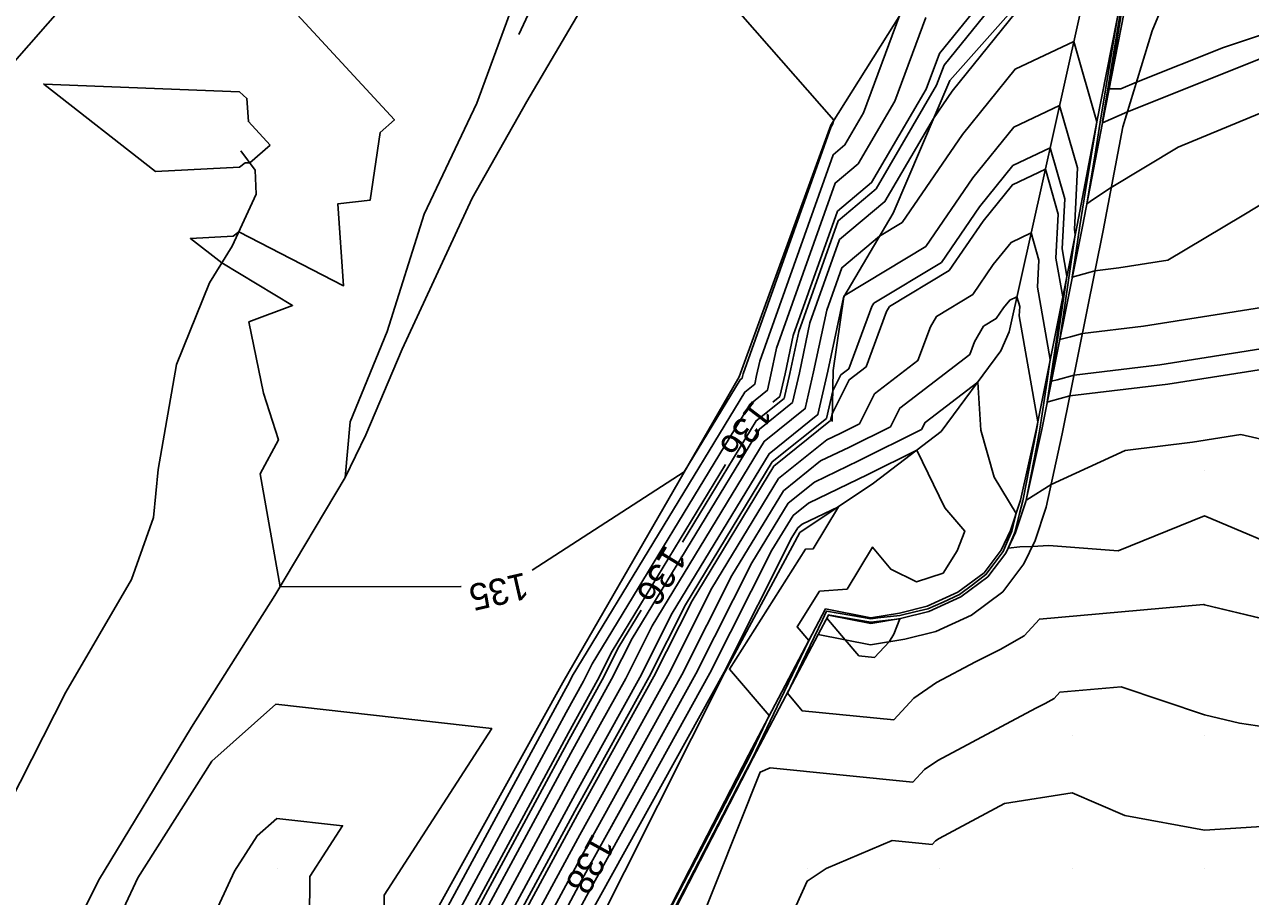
# Model space of a CAD drawing. Extents: x 2354170 to 2357230, y 866100 to 868290.
# Drawn here: x 2354670.9 to 2354763.4, y 867567.9 to 867633.7 of the extents above; entities that cross this region are included whole.
import ezdxf

# ---------------------------------------------------------------- set-up
doc = ezdxf.new("R2010")
doc.units = 0
for name, color, linetype in [('Default', 7, 'Continuous'), ('DTM Contours Major', 7, 'Continuous'), ('DTM Contours Major Text', 7, 'Continuous'), ('DTM Contours Minor', 7, 'Continuous'), ('DTM Contours Minor Text', 7, 'Continuous'), ('Exist DTM QL2 LIDAR Elevation Point', 7, 'Continuous'), ('PH Exist DTM Breakline', 7, 'Continuous')]:
    doc.layers.add(name, color=color, linetype=linetype)

msp = doc.modelspace()

# ---------------------------------------------------------------- linework, layer by layer
at = {"layer": 'Default'}
for points in [[(2354753.289, 867645.149), (2354753.89, 867644.723), (2354753.715, 867644.159), (2354753.483, 867644.183), (2354752.387, 867644.712), (2354749.577, 867645.426), (2354745.199, 867646.843), (2354737.675, 867651.174), (2354735.499, 867649.204), (2354724.939, 867645.727), (2354721.135, 867638.857), (2354732, 867626.487), (2354731.877, 867626.156), (2354731.813, 867626.047), (2354731.774, 867626.014), (2354725.132, 867607.354), (2354725.087, 867607.143), (2354725.059, 867607.018), (2354724.918, 867606.906), (2354720.686, 867599.939), (2354709.214, 867592.527)], [(2354703.858, 867591.296), (2354703.825, 867591.305), (2354690.194, 867591.273), (2354688.692, 867599.791), (2354690.055, 867602.378), (2354688.937, 867605.884), (2354687.836, 867611.265), (2354691.132, 867612.495), (2354685.781, 867615.714), (2354683.422, 867617.564), (2354686.642, 867617.728), (2354687.065, 867618.056), (2354694.979, 867613.992), (2354694.546, 867620.18), (2354696.987, 867620.459), (2354697.732, 867625.558), (2354698.816, 867626.509), (2354690.241, 867635.818), (2354690.032, 867638.88), (2354688.601, 867641.962), (2354688.404, 867642.089), (2354688.216, 867642.692), (2354690.195, 867646.304), (2354690.52, 867647.046)], [(2354669.967, 867630.717), (2354677.868, 867639.745)], [(2354772.251, 867634.306), (2354768.905, 867633.644), (2354767.48, 867634.023), (2354761.394, 867631.986), (2354754.84, 867629.368), (2354753.641, 867628.845), (2354752.763, 867628.867), (2354754.241, 867637.936)], [(2354743.213, 867635.533), (2354739.968, 867631.535), (2354738.962, 867628.825), (2354734.839, 867621.775), (2354732.262, 867619.615), (2354728.923, 867610.234), (2354728.312, 867607.351), (2354727.924, 867605.645), (2354727.389, 867605.217)], [(2354745.77, 867634.683), (2354740.932, 867628.688), (2354739.506, 867626.605), (2354735.848, 867620.351), (2354732.424, 867617.482), (2354730.186, 867611.194), (2354729.387, 867607.421), (2354728.879, 867605.187), (2354726.369, 867603.182), (2354716.763, 867587.372), (2354715.214, 867584.296), (2354712.123, 867578.711), (2354705.438, 867566.346), (2354701.758, 867560.163), (2354693.163, 867547.394), (2354691.86, 867545.154), (2354681.834, 867526.589), (2354679.548, 867527.524), (2354677.78, 867522.793), (2354675.617, 867520.767), (2354672.657, 867519.107), (2354671.849, 867517.269), (2354671.575, 867515.082), (2354662.843, 867505.021)], [(2354736.981, 867634.44), (2354734.239, 867627.046), (2354732.822, 867624.623), (2354731.936, 867623.881), (2354726.395, 867608.314), (2354726.162, 867607.212), (2354726.014, 867606.56), (2354725.281, 867605.975), (2354712.244, 867584.517), (2354712.032, 867584.095), (2354711.608, 867583.329), (2354702.71, 867566.871), (2354702.003, 867565.681), (2354697.987, 867559.716), (2354698.049, 867567.998), (2354706.16, 867580.568), (2354689.864, 867582.409), (2354685.044, 867578.12), (2354679.442, 867569.314), (2354677.287, 867564.679), (2354672.889, 867556.61), (2354670.739, 867550.602)], [(2354703.619, 867566.696), (2354711.779, 867581.79), (2354713.092, 867584.162), (2354713.75, 867585.469), (2354725.644, 867605.044), (2354726.969, 867606.102), (2354727.237, 867607.282), (2354727.659, 867609.274), (2354732.099, 867621.748), (2354733.831, 867623.199), (2354736.601, 867627.936), (2354738.94, 867634.244)], [(2354769.969, 867629.419), (2354757.986, 867624.455), (2354752.932, 867621.408), (2354751.586, 867620.519), (2354751.084, 867620.187), (2354751.754, 867624.247), (2354752.097, 867626.329), (2354753.364, 867634.107)], [(2354766.302, 867621.375), (2354762.808, 867619.269), (2354757.189, 867615.918), (2354753.504, 867615.338), (2354751.697, 867615.119), (2354751.34, 867615.023), (2354749.987, 867614.643), (2354750.18, 867615.955), (2354750.555, 867618.516), (2354750.994, 867621.177), (2354751.849, 867626.364), (2354751.85, 867626.372), (2354750.104, 867632.416), (2354745.67, 867630.328), (2354741.705, 867625.414), (2354737.156, 867618.774), (2354735.442, 867617.742), (2354732.587, 867615.349), (2354731.45, 867612.154), (2354730.462, 867607.491), (2354729.835, 867604.729), (2354726.731, 867602.251), (2354718.269, 867588.323), (2354716.275, 867584.363), (2354712.294, 867577.172), (2354706.347, 867566.171)], [(2354689.437, 867624.612), (2354687.802, 867626.387), (2354687.682, 867628.134), (2354687.134, 867628.62), (2354672.342, 867629.213), (2354680.774, 867622.614), (2354687.116, 867622.937), (2354687.545, 867623.27), (2354687.898, 867623.263), (2354689.437, 867624.612)], [(2354764.74, 867612.432), (2354755.354, 867610.954), (2354750.752, 867610.398), (2354749.841, 867610.151), (2354749.043, 867609.927), (2354749.472, 867612.855), (2354750.208, 867617.867), (2354750.143, 867618.239), (2354750.392, 867622.887), (2354749.029, 867627.603), (2354745.571, 867625.974), (2354742.477, 867622.14), (2354738.928, 867616.961), (2354732.841, 867613.293), (2354732.75, 867613.216), (2354732.713, 867613.114), (2354731.537, 867607.56), (2354730.79, 867604.271), (2354727.094, 867601.32), (2354719.776, 867589.275), (2354717.335, 867584.43), (2354712.466, 867575.633), (2354707.256, 867565.996)], [(2354731.745, 867603.813), (2354731.876, 867604.389), (2354733.142, 867606.905), (2354734.417, 867607.88), (2354735.967, 867612.043), (2354736.183, 867612.425), (2354740.701, 867615.147), (2354743.25, 867618.866), (2354745.471, 867621.62), (2354747.955, 867622.79), (2354748.933, 867619.403), (2354748.755, 867616.065), (2354749.264, 867613.153), (2354748.765, 867609.754), (2354748.098, 867605.212), (2354748.343, 867605.28), (2354749.806, 867605.676), (2354757.204, 867606.57), (2354768.262, 867608.311)], [(2354727.819, 867599.457), (2354731.458, 867602.364), (2354732.47, 867602.853), (2354733.913, 867603.567), (2354735.052, 867605.831), (2354738.336, 867608.344), (2354739.29, 867610.903), (2354739.729, 867611.679), (2354742.474, 867613.333), (2354744.022, 867615.593), (2354745.372, 867617.266), (2354746.881, 867617.976), (2354747.475, 867615.919), (2354747.367, 867613.89), (2354748.32, 867608.439), (2354748.058, 867606.653), (2354747.546, 867603.162), (2354747.284, 867601.804), (2354746.514, 867597.806), (2354746.564, 867597.84), (2354748.397, 867599.002), (2354753.983, 867601.573), (2354759.053, 867602.186), (2354762.713, 867602.763), (2354779.226, 867599.002)], [(2354728.181, 867598.526), (2354730.993, 867600.772), (2354733.163, 867601.82), (2354736.254, 867603.351), (2354736.962, 867604.758), (2354742.256, 867608.808), (2354742.612, 867609.763), (2354743.274, 867610.933), (2354744.246, 867611.519), (2354744.795, 867612.319), (2354745.273, 867612.911), (2354745.807, 867613.163), (2354746.017, 867612.434), (2354745.979, 867611.716), (2354747.376, 867603.725), (2354747.35, 867603.552), (2354747.301, 867603.214), (2354746.572, 867599.426), (2354746.253, 867597.771), (2354746.01, 867596.806), (2354745.651, 867595.39), (2354745.572, 867595.199), (2354745.155, 867594.192), (2354746.035, 867594.279), (2354746.963, 867594.313), (2354748.209, 867594.393), (2354753.447, 867593.983), (2354759.968, 867596.635), (2354774.521, 867590.481)], [(2354728.544, 867597.595), (2354730.528, 867599.18), (2354733.855, 867600.787), (2354738.596, 867603.135), (2354738.873, 867603.685), (2354742.852, 867606.729), (2354743.096, 867603.09), (2354744.082, 867599.551), (2354745.753, 867596.811), (2354745.524, 867595.898), (2354745.419, 867595.484), (2354745.028, 867594.536), (2354744.783, 867593.944), (2354744.092, 867593.024), (2354743.467, 867592.192), (2354742.45, 867591.426), (2354741.462, 867590.681), (2354740.231, 867590.122), (2354739.093, 867589.605), (2354738.106, 867589.378), (2354736.975, 867589.118), (2354735.302, 867588.921), (2354734.789, 867588.86), (2354734.081, 867588.979), (2354731.439, 867589.437), (2354731.125, 867588.782), (2354729.566, 867585.524), (2354728.478, 867583.249), (2354729.594, 867581.925), (2354736.506, 867581.238), (2354738.018, 867582.877), (2354739.748, 867584.039), (2354742.69, 867585.604), (2354744.535, 867586.542), (2354746.348, 867587.562), (2354747.504, 867588.835), (2354759.898, 867589.947), (2354759.968, 867589.924), (2354772.257, 867586.981)], [(2354705.24, 867560.904), (2354708.165, 867565.821), (2354712.637, 867574.093), (2354718.396, 867584.496), (2354721.282, 867590.226), (2354727.456, 867600.389), (2354731.745, 867603.813)], [(2354728.906, 867596.664), (2354730.063, 867597.588), (2354734.548, 867599.754), (2354738.257, 867601.591), (2354740.375, 867597.233), (2354741.881, 867595.48), (2354741.289, 867593.987), (2354740.239, 867592.306), (2354738.219, 867591.657), (2354736.282, 867592.595), (2354734.895, 867594.268), (2354732.988, 867591.09), (2354730.909, 867590.935), (2354729.212, 867588.256), (2354730.102, 867587.223), (2354727.972, 867582.77), (2354725.875, 867578.386), (2354725.075, 867576.849), (2354717.812, 867562.877)], [(2354723.809, 867600.497), (2354715.257, 867586.42), (2354714.153, 867584.229), (2354711.951, 867580.251), (2354704.529, 867566.521), (2354701.84, 867562.002), (2354692.433, 867548.027), (2354691.812, 867546.96), (2354687.037, 867538.118), (2354679.801, 867541.078), (2354674.203, 867526.101), (2354673.03, 867525.003), (2354671.181, 867523.966)], [(2354685.572, 867489.55), (2354682.471, 867491.723), (2354675.058, 867496.562), (2354674.059, 867500.46), (2354674.095, 867501.357), (2354679.343, 867513.255), (2354682.271, 867519.818), (2354683.758, 867522.572), (2354692.051, 867537.928), (2354696.086, 867544.862), (2354701.433, 867552.805), (2354709.075, 867565.646), (2354712.809, 867572.554), (2354719.457, 867584.563), (2354722.788, 867591.178), (2354727.819, 867599.457)], [(2354687.15, 867489.608), (2354682.472, 867492.886), (2354676.177, 867496.995), (2354675.329, 867500.305), (2354675.389, 867501.823), (2354679.862, 867511.964), (2354683.704, 867520.578), (2354684.981, 867522.941), (2354692.099, 867536.122), (2354696.817, 867544.229), (2354701.351, 867550.965), (2354709.984, 867565.471), (2354712.981, 867571.014), (2354720.518, 867584.63), (2354724.295, 867592.129), (2354728.181, 867598.526)], [(2354715.063, 867572.926), (2354721.578, 867584.697), (2354725.801, 867593.081), (2354728.544, 867597.595)], [(2354690.304, 867489.724), (2354682.473, 867495.212), (2354678.414, 867497.861), (2354677.867, 867499.996), (2354677.977, 867502.755), (2354680.9, 867509.383), (2354686.571, 867522.096), (2354687.426, 867523.68), (2354692.194, 867532.509), (2354698.278, 867542.963), (2354701.188, 867547.287), (2354711.802, 867565.121), (2354713.324, 867567.936), (2354722.639, 867584.764), (2354727.307, 867594.032), (2354728.906, 867596.664)], [(2354729.269, 867595.733), (2354729.598, 867595.996), (2354732.335, 867597.318), (2354730.431, 867594.146), (2354729.839, 867594.102), (2354724.105, 867585.046), (2354727.112, 867581.553), (2354726.377, 867580.015), (2354725.653, 867578.502), (2354719.117, 867565.929)], [(2354691.881, 867489.782), (2354682.474, 867496.374), (2354679.533, 867498.294), (2354679.137, 867499.841), (2354679.271, 867503.221), (2354681.419, 867508.093), (2354688.005, 867522.856), (2354688.649, 867524.049), (2354692.242, 867530.702), (2354699.009, 867542.33), (2354701.107, 867545.447), (2354712.712, 867564.946), (2354713.496, 867566.396), (2354723.7, 867584.831), (2354728.814, 867594.984), (2354729.269, 867595.733)], [(2354736.977, 867588.867), (2354734.785, 867588.606), (2354731.675, 867589.131), (2354731.577, 867589.148), (2354731.467, 867588.918), (2354732.851, 867587.275), (2354733.879, 867586.056), (2354735.055, 867585.939), (2354736.154, 867587.13), (2354736.525, 867587.703), (2354736.977, 867588.867)], [(2354721.521, 867564.987), (2354726.432, 867577.287), (2354727.189, 867577.608), (2354737.957, 867576.537), (2354738.835, 867577.489), (2354739.84, 867578.164), (2354747.247, 867582.107), (2354747.936, 867582.457), (2354748.615, 867582.839), (2354749.047, 867583.315), (2354753.682, 867583.731), (2354759.968, 867581.613), (2354762.622, 867580.978), (2354764.66, 867580.684)], [(2354726.264, 867560.881), (2354729.968, 867569.066), (2354731.411, 867570.017), (2354736.403, 867572.135), (2354739.407, 867571.836), (2354739.652, 867572.102), (2354739.933, 867572.29), (2354744.868, 867574.917), (2354749.968, 867575.734), (2354753.963, 867574.012), (2354759.968, 867572.913), (2354766.646, 867573.339)], [(2354679.287, 867553.741), (2354686.756, 867569.803), (2354688.465, 867572.49), (2354689.936, 867573.799), (2354694.909, 867573.237), (2354692.434, 867569.401), (2354692.285, 867549.526)]]:
    msp.add_lwpolyline(points, dxfattribs=at)
at = {"layer": 'DTM Contours Major'}
for points in [[(2354753.289, 867645.149), (2354753.89, 867644.723), (2354753.715, 867644.159), (2354753.483, 867644.183), (2354752.387, 867644.712), (2354749.577, 867645.426), (2354745.199, 867646.843), (2354737.675, 867651.174), (2354735.499, 867649.204), (2354724.939, 867645.727), (2354721.135, 867638.857), (2354732, 867626.487), (2354731.877, 867626.156), (2354731.813, 867626.047), (2354731.774, 867626.014), (2354725.132, 867607.354), (2354725.087, 867607.143), (2354725.059, 867607.018), (2354724.918, 867606.906), (2354720.686, 867599.939), (2354709.214, 867592.527)], [(2354703.858, 867591.296), (2354703.825, 867591.305), (2354690.194, 867591.273), (2354688.692, 867599.791), (2354690.055, 867602.378), (2354688.937, 867605.884), (2354687.836, 867611.265), (2354691.132, 867612.495), (2354685.781, 867615.714), (2354683.422, 867617.564), (2354686.642, 867617.728), (2354687.065, 867618.056), (2354694.979, 867613.992), (2354694.546, 867620.18), (2354696.987, 867620.459), (2354697.732, 867625.558), (2354698.816, 867626.509), (2354690.241, 867635.818), (2354690.032, 867638.88), (2354688.601, 867641.962), (2354688.404, 867642.089), (2354688.216, 867642.692), (2354690.195, 867646.304), (2354690.52, 867647.046)]]:
    msp.add_lwpolyline(points, dxfattribs=at)
at = {"layer": 'DTM Contours Minor'}
for points in [[(2354781.134, 867634.172), (2354779.766, 867633.414), (2354778.958, 867633.082), (2354776.788, 867632.134), (2354776.453, 867631.963), (2354776.243, 867631.88), (2354773.332, 867632.336), (2354771.413, 867632.732), (2354769.295, 867632.313), (2354768.393, 867632.553), (2354764.541, 867631.264), (2354754.155, 867627.115), (2354752.274, 867626.295), (2354752.258, 867626.285), (2354752.26, 867626.294), (2354752.26, 867626.298), (2354752.276, 867626.394), (2354754.159, 867637.952)], [(2354744.168, 867635.386), (2354740.31, 867630.633), (2354739.75, 867629.122), (2354735.175, 867621.301), (2354732.316, 867618.904), (2354729.344, 867610.554), (2354728.67, 867607.375), (2354728.243, 867605.492), (2354726.127, 867603.802), (2354720.561, 867594.641)], [(2354731.427, 867603.966), (2354731.904, 867606.069), (2354732.505, 867607.262), (2354733.11, 867607.725), (2354734.86, 867612.423), (2354735.001, 867612.673), (2354740.11, 867615.751), (2354742.992, 867619.958), (2354745.505, 867623.071), (2354748.313, 867624.394), (2354749.419, 867620.565), (2354749.218, 867616.789), (2354749.579, 867614.724), (2354749.001, 867610.787), (2354748.413, 867606.783), (2354748.842, 867606.904), (2354750.121, 867607.25), (2354756.587, 867608.031), (2354769.774, 867610.108)], [(2354728.544, 867597.595), (2354730.528, 867599.18), (2354733.855, 867600.787), (2354738.596, 867603.135), (2354738.873, 867603.685), (2354742.852, 867606.729), (2354743.096, 867603.09), (2354744.082, 867599.551), (2354745.753, 867596.811), (2354745.524, 867595.898), (2354745.419, 867595.484), (2354745.028, 867594.536), (2354744.783, 867593.944), (2354744.092, 867593.024), (2354743.467, 867592.192), (2354742.45, 867591.426), (2354741.462, 867590.681), (2354740.231, 867590.122), (2354739.093, 867589.605), (2354738.106, 867589.378), (2354736.975, 867589.118), (2354735.302, 867588.921), (2354734.789, 867588.86), (2354734.081, 867588.979), (2354731.439, 867589.437), (2354731.125, 867588.782), (2354729.566, 867585.524), (2354728.478, 867583.249), (2354729.594, 867581.925), (2354736.506, 867581.238), (2354738.018, 867582.877), (2354739.748, 867584.039), (2354742.69, 867585.604), (2354744.535, 867586.542), (2354746.348, 867587.562), (2354747.504, 867588.835), (2354759.898, 867589.947), (2354759.968, 867589.924), (2354776.443, 867585.978)], [(2354720.259, 867466.24), (2354706.626, 867476.082), (2354705.641, 867476.677), (2354699.334, 867479.414), (2354697.435, 867480.463), (2354683.469, 867489.473), (2354682.47, 867490.173), (2354673.566, 867495.985), (2354672.367, 867500.667), (2354672.37, 867500.736), (2354678.651, 867514.975), (2354680.36, 867518.806), (2354682.128, 867522.08), (2354691.987, 867540.336), (2354695.112, 867545.706), (2354701.541, 867555.258), (2354707.862, 867565.879), (2354712.58, 867574.606), (2354718.043, 867584.474), (2354720.78, 867589.909), (2354727.335, 867600.699), (2354731.427, 867603.966)], [(2354710.157, 867477.416), (2354708.532, 867478.397), (2354704.849, 867479.996), (2354696.983, 867484.34), (2354688.727, 867489.666), (2354682.473, 867494.049), (2354677.295, 867497.428), (2354676.598, 867500.15), (2354676.683, 867502.289), (2354680.381, 867510.674), (2354685.138, 867521.337), (2354686.204, 867523.311), (2354692.146, 867534.315), (2354697.548, 867543.596), (2354701.27, 867549.126), (2354710.893, 867565.296), (2354713.152, 867569.475), (2354721.578, 867584.697), (2354725.801, 867593.081), (2354728.544, 867597.595)], [(2354717.446, 867589.514), (2354715.759, 867586.737), (2354714.507, 867584.251), (2354712.008, 867579.738), (2354704.832, 867566.462), (2354701.813, 867561.389), (2354692.676, 867547.816), (2354691.828, 867546.358), (2354685.303, 867534.275), (2354679.717, 867536.56), (2354675.395, 867524.998), (2354673.892, 867523.591), (2354668.461, 867520.544)]]:
    msp.add_lwpolyline(points, dxfattribs=at)
at = {"layer": 'Exist DTM QL2 LIDAR Elevation Point'}
for p, q in [((2354759.968, 867600.018), (2354759.968, 867600.018)), ((2354759.968, 867590.017), (2354759.968, 867590.017)), ((2354749.968, 867580.017), (2354749.968, 867580.017)), ((2354759.968, 867580.017), (2354759.968, 867580.017)), ((2354689.968, 867570.017), (2354689.968, 867570.017)), ((2354729.968, 867570.017), (2354729.968, 867570.017)), ((2354739.968, 867570.017), (2354739.968, 867570.017)), ((2354749.968, 867570.017), (2354749.968, 867570.017)), ((2354759.968, 867570.017), (2354759.968, 867570.017))]:
    msp.add_line(p, q, dxfattribs=at)
at = {"layer": 'PH Exist DTM Breakline'}
for p, q in [((2354751.852, 867626.377), (2354754.118, 867637.96)), ((2354752.261, 867626.298), (2354754.527, 867637.88))]:
    msp.add_line(p, q, dxfattribs=at)
for points in [[(2354708.221, 867632.948), (2354712.344, 867641.814), (2354717.715, 867652.332), (2354721.936, 867661.543), (2354722.309, 867663.296)], [(2354754.118, 867637.96), (2354753.744, 867641.141), (2354752.778, 867642.129), (2354744.152, 867646.615), (2354734.656, 867653.3), (2354729.343, 867657.983), (2354725.013, 867660.602), (2354720.232, 867649.079), (2354715.727, 867639.665), (2354708.808, 867627.903), (2354704.684, 867620.603), (2354699.404, 867609.199), (2354696.662, 867602.739), (2354695.094, 867599.514)], [(2354753.816, 867625.999), (2354756.012, 867633.222), (2354758.46, 867639.139)], [(2354829.923, 867427.32), (2354817.709, 867428.865), (2354759.654, 867457.926), (2354748.772, 867463.94), (2354718.087, 867477.789), (2354712.589, 867480.813), (2354696.33, 867489.946), (2354682.476, 867499.433), (2354682.859, 867504.514), (2354692.388, 867525.178), (2354700.896, 867540.695), (2354713.678, 867564.76), (2354723.77, 867584.835), (2354729.413, 867595.363), (2354734.99, 867599.095), (2354740.097, 867602.997), (2354744.591, 867609.084), (2354745.218, 867610.524), (2354751.239, 867637.503)], [(2354738.155, 867636.314), (2354731.766, 867626.114), (2354724.833, 867607.126), (2354711.526, 867584.063), (2354702.061, 867566.996), (2354691.768, 867548.603), (2354677.681, 867517.387), (2354672.226, 867500.684), (2354673.389, 867495.916), (2354682.47, 867489.436), (2354697.578, 867479.229), (2354703.979, 867475.688), (2354722.591, 867463.336), (2354738.582, 867453.622), (2354742.679, 867450.771), (2354747.113, 867448.158), (2354755.857, 867445.272), (2354761.221, 867443.293), (2354770.34, 867439.958), (2354791.969, 867430.541), (2354800.951, 867426.618), (2354813.493, 867420.185), (2354830.452, 867410.182)], [(2354667.129, 867550.83), (2354671.124, 867558.254), (2354676.476, 867569.116), (2354683.493, 867580.672), (2354689.796, 867590.605), (2354695.094, 867599.514), (2354695.479, 867603.726), (2354698.261, 867610.547), (2354701.075, 867619.398), (2354705.047, 867627.769), (2354707.735, 867635.093)], [(2354745.78, 867635.137), (2354740.741, 867629.496), (2354736.461, 867619.485), (2354732.755, 867613.146), (2354731.93, 867607.586), (2354731.865, 867603.756)], [(2354751.852, 867626.377), (2354750.346, 867618.557), (2354747.275, 867603.219), (2354746.089, 867597.816), (2354745.323, 867595.522), (2354744.622, 867594.041), (2354743.326, 867592.335), (2354741.351, 867590.869), (2354739.023, 867589.805), (2354736.941, 867589.283), (2354734.79, 867588.935), (2354731.358, 867589.605)], [(2354752.261, 867626.298), (2354750.755, 867618.477), (2354747.682, 867603.134), (2354746.492, 867597.705), (2354745.71, 867595.367), (2354744.98, 867593.824), (2354743.622, 867592.036), (2354741.564, 867590.508), (2354739.162, 867589.41), (2354737.025, 867588.875), (2354734.784, 867588.511), (2354731.582, 867589.137)], [(2354753.816, 867625.999), (2354752.309, 867618.172), (2354749.232, 867602.808), (2354748.02, 867597.283), (2354747.182, 867594.775), (2354746.341, 867592.997), (2354744.747, 867590.899), (2354742.374, 867589.137), (2354739.688, 867587.909), (2354737.344, 867587.323), (2354734.758, 867586.903), (2354730.811, 867587.674)], [(2354687.227, 867624.165), (2354688.309, 867622.71), (2354688.381, 867620.919), (2354686.575, 867616.989), (2354684.848, 867614.213), (2354682.376, 867608.049), (2354680.994, 867600.125), (2354680.629, 867596.5), (2354678.974, 867591.817), (2354674.018, 867583.328), (2354667.98, 867571.476)], [(2354731.358, 867589.605), (2354725.536, 867578.563), (2354717.532, 867563.023), (2354706.067, 867541.136)], [(2354731.582, 867589.137), (2354730.811, 867587.674)], [(2354730.811, 867587.674), (2354725.905, 867578.37), (2354717.901, 867562.831), (2354706.436, 867540.943)]]:
    msp.add_lwpolyline(points, dxfattribs=at)

# ---------------------------------------------------------------- texts
at = {"layer": 'Default'}
for s, rotation, p in [('136', 232.82369, (2354725.926, 867605.453)), ('135', 192.94615, (2354708.657, 867592.376)), ('138', 241.2291, (2354713.813, 867572.75))]:
    msp.add_text(s, height=2, rotation=rotation, dxfattribs=at).set_placement(p)
at = {"layer": 'DTM Contours Major Text'}
msp.add_text('135', height=2, rotation=192.94615, dxfattribs=at).set_placement((2354708.657, 867592.376))
at = {"layer": 'DTM Contours Minor Text'}
msp.add_text('136', height=2, rotation=238.71864, dxfattribs=at).set_placement((2354719.314, 867594.515))

doc.saveas('drawing.dxf')
